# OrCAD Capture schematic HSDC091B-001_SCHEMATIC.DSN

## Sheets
1 1. PAGE1: size B; title: TMUXHS4212EVM; rev: A; note: HSDC091B
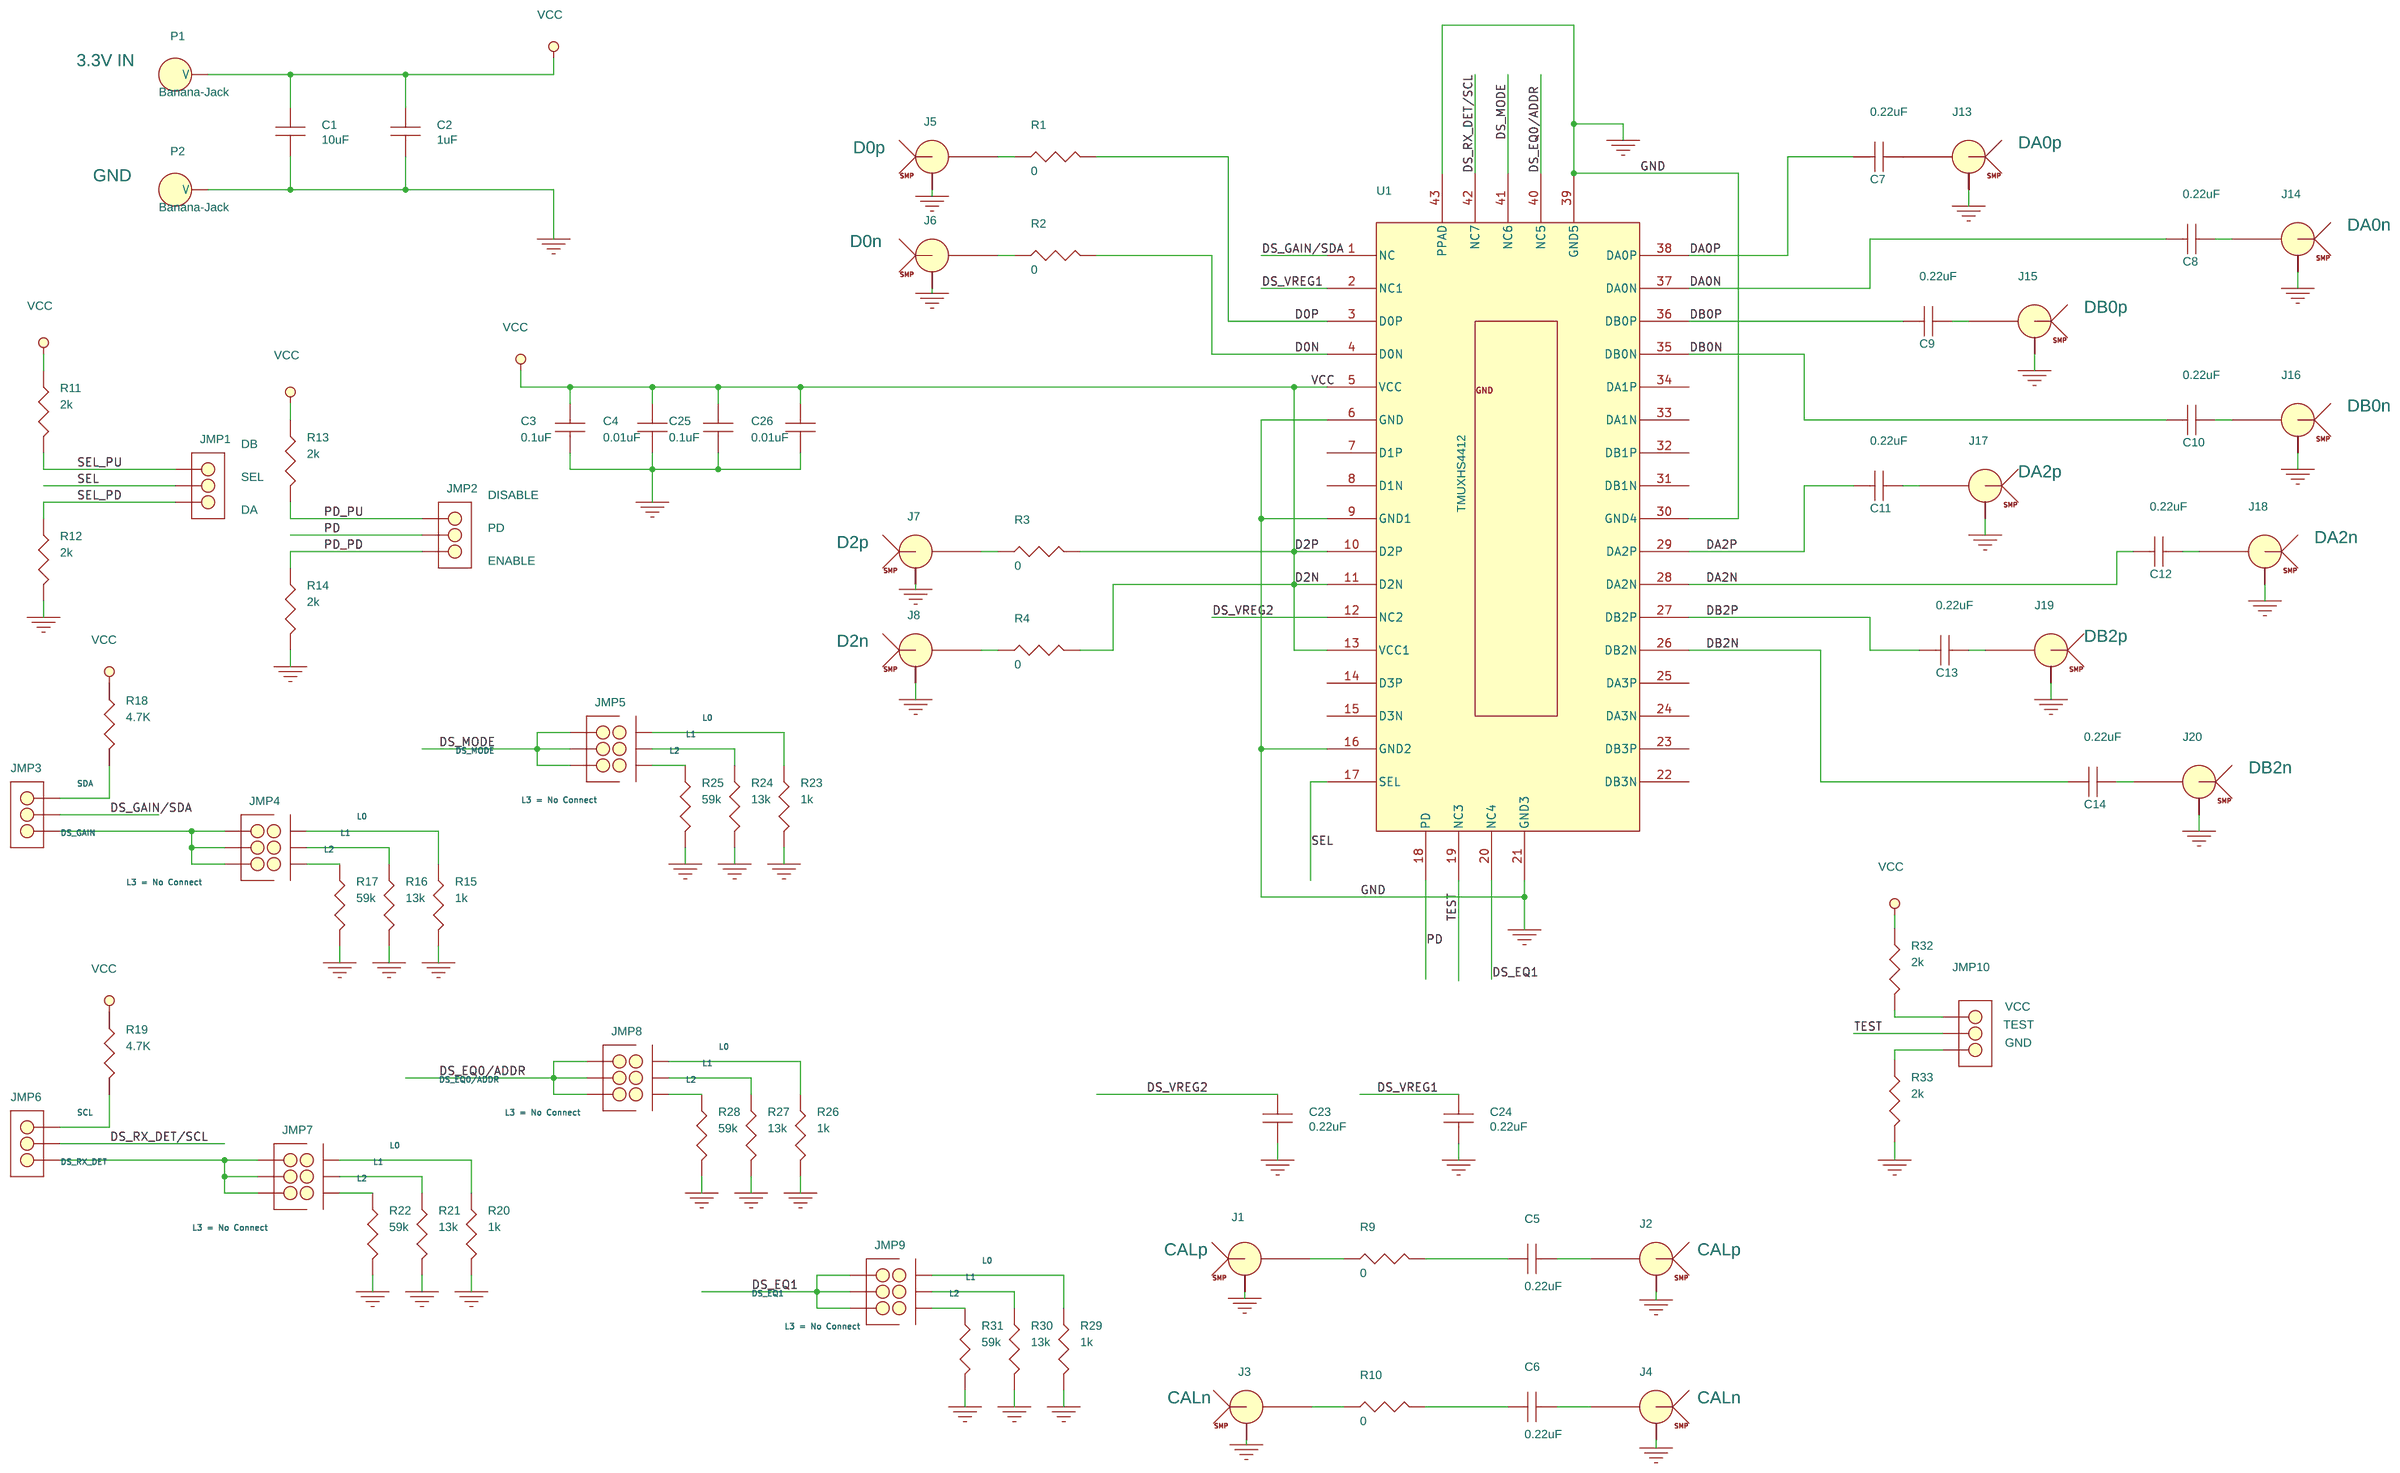
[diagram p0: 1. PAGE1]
2 2. HARDWARE: title: TMUXHS4412EVM - Hardware and Assembly Notes; note: HDSC091B
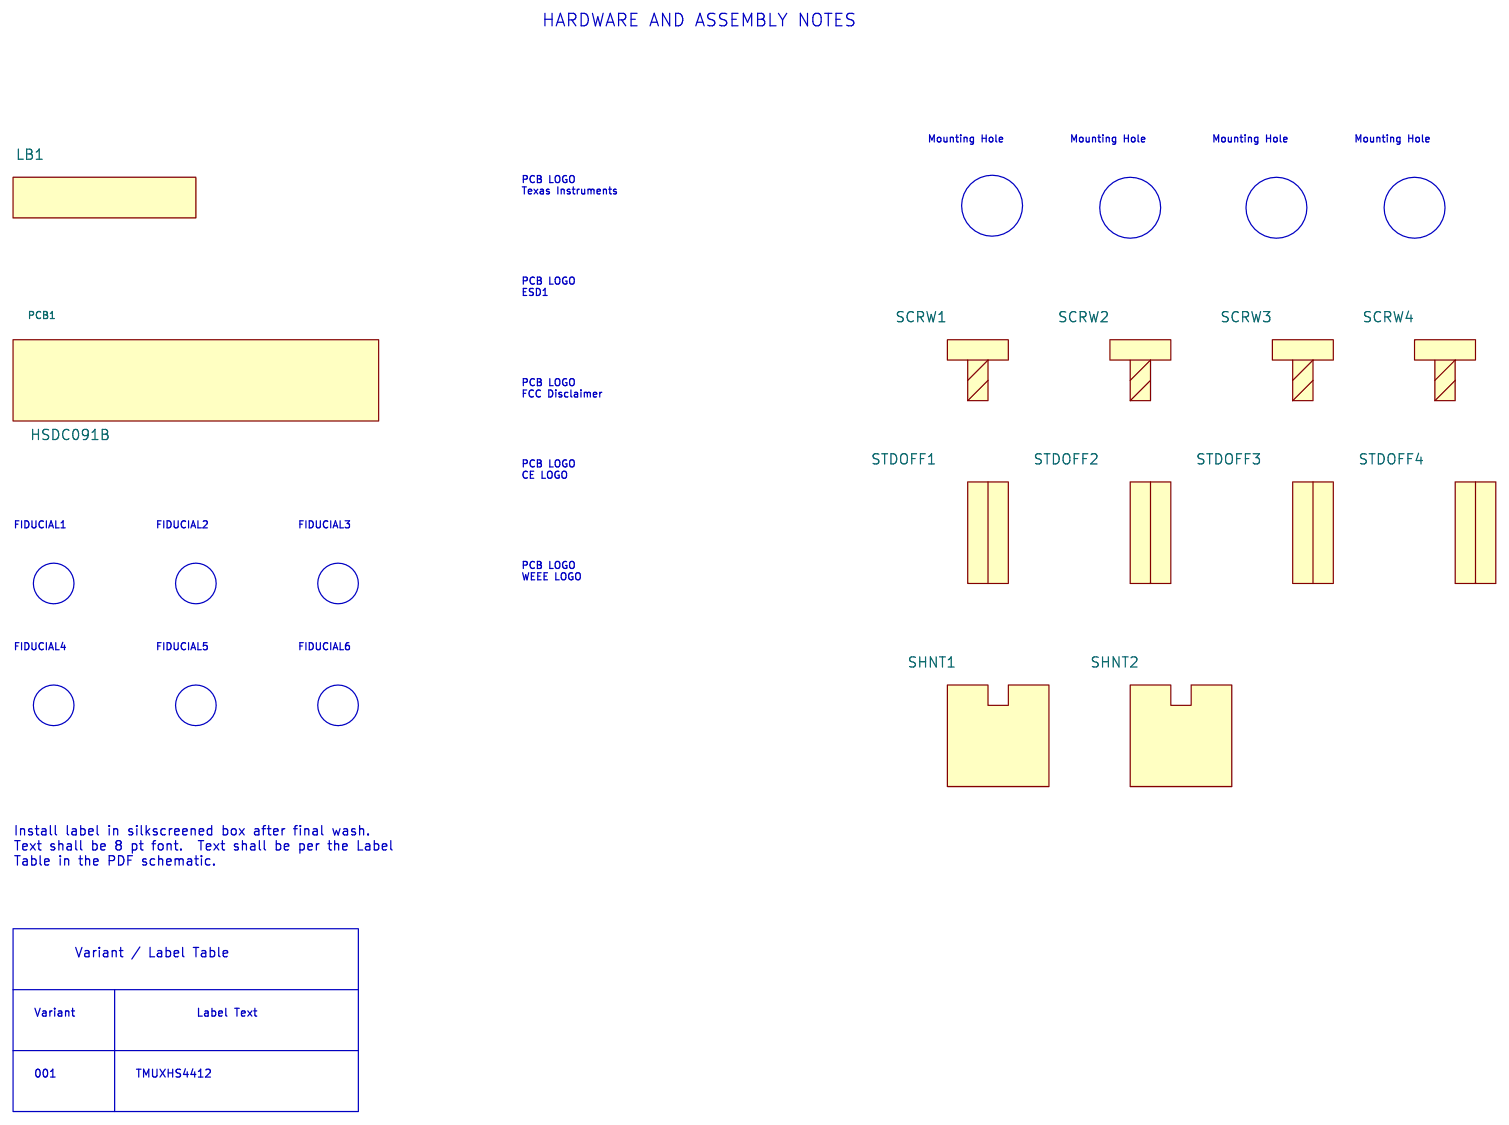
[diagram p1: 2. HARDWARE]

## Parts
sheet 1. PAGE1
C1  10uF  [cap_0603]
C2  1uF  [cap_0603]
C3  0.1uF  [cap_0402]
C4  0.01uF  [cap_0402]
C5  0.22uF  [cap_0201]
C6  0.22uF  [cap_0201]
C7  0.22uF  [cap_0201]
C8  0.22uF  [cap_0201]
C9  0.22uF  [cap_0201]
C10  0.22uF  [cap_0201]
C11  0.22uF  [cap_0201]
C12  0.22uF  [cap_0201]
C13  0.22uF  [cap_0201]
C14  0.22uF  [cap_0201]
C23  0.22uF  [cap_0603]
C24  0.22uF  [cap_0603]
C25  0.1uF  [cap_0402]
C26  0.01uF  [cap_0402]
J1  SMP  [CON_SMVT_19S101-40ML5_R04350]
J2  SMP  [CON_SMVT_19S101-40ML5_R04350]
J3  SMP  [CON_SMVT_19S101-40ML5_R04350]
J4  SMP  [CON_SMVT_19S101-40ML5_R04350]
J5  SMP  [CON_SMVT_19S101-40ML5_R04350]
J6  SMP  [CON_SMVT_19S101-40ML5_R04350]
J7  SMP  [CON_SMVT_19S101-40ML5_R04350]
J8  SMP  [CON_SMVT_19S101-40ML5_R04350]
J13  SMP  [CON_SMVT_19S101-40ML5_R04350]
J14  SMP  [CON_SMVT_19S101-40ML5_R04350]
J15  SMP  [CON_SMVT_19S101-40ML5_R04350]
J16  SMP  [CON_SMVT_19S101-40ML5_R04350]
J17  SMP  [CON_SMVT_19S101-40ML5_R04350]
J18  SMP  [CON_SMVT_19S101-40ML5_R04350]
J19  SMP  [CON_SMVT_19S101-40ML5_R04350]
J20  SMP  [CON_SMVT_19S101-40ML5_R04350]
JMP1  HDR3X1 M .1  [HDR_THVT_1X3_254_871]
JMP2  HDR3X1 M .1  [HDR_THVT_1X3_254_871]
JMP3  HDR3X1 M .1  [HDR_THVT_1X3_254_871]
JMP4  HDR3X1 M .1  [HDR_THVT_2X3_254_871]
JMP5  HDR3X1 M .1  [HDR_THVT_2X3_254_871]
JMP6  HDR3X1 M .1  [HDR_THVT_1X3_254_871]
JMP7  HDR3X1 M .1  [HDR_THVT_2X3_254_871]
JMP8  HDR3X1 M .1  [HDR_THVT_2X3_254_871]
JMP9  HDR3X1 M .1  [HDR_THVT_2X3_254_871]
JMP10  HDR3X1 M .1  [HDR_THVT_1X3_254_871]
P1  Banana-Jack  [BJ_THVT_3267]
P2  Banana-Jack  [BJ_THVT_3267]
R1  0  [res_0201]
R2  0  [res_0201]
R3  0  [res_0201]
R4  0  [res_0201]
R9  0  [res_0201]
R10  0  [res_0201]
R11  2k  [res_0402]
R12  2k  [res_0402]
R13  2k  [res_0402]
R14  2k  [res_0402]
R15  1k  [res_0402]
R16  13k  [res_0402]
R17  59k  [res_0402]
R18  4.7K  [res_0402]
R19  4.7K  [res_0402]
R20  1k  [res_0402]
R21  13k  [res_0402]
R22  59k  [res_0402]
R23  1k  [res_0402]
R24  13k  [res_0402]
R25  59k  [res_0402]
R26  1k  [res_0402]
R27  13k  [res_0402]
R28  59k  [res_0402]
R29  1k  [res_0402]
R30  13k  [res_0402]
R31  59k  [res_0402]
R32  2k  [res_0402]
R33  2k  [res_0402]
U1  TMUXHS4412  [RUA0042BA_205x755]
sheet 2. HARDWARE
LB1  PCB Label 0.650"H x 0.200"W  [rectangle]
PCB1  HSDC091B  [n/a]
SCRW1  NY PMS 440 005 PH  [screw]
SCRW2  NY PMS 440 005 PH  [screw]
SCRW3  NY PMS 440 005 PH  [screw]
SCRW4  NY PMS 440 005 PH  [screw]
SHNT1  QPC02SXGN-RC  [.1]
SHNT2  QPC02SXGN-RC  [.1]
STDOFF1  1902E  [Standoff]
STDOFF2  1902E  [Standoff]
STDOFF3  1902E  [Standoff]
STDOFF4  1902E  [Standoff]

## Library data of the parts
C1 = cc0603: Digikey: 587-1242-1-ND; Manufacturer: Murata; Manufacturer Part Number: GRM188R61A106KE69D
C2 C23 C24 = cc0603: Digikey: 587-1242-1-ND; Manufacturer: Taiyo Yuden; Manufacturer Part Number: LMK107B7105KA-T
C3 C25 = cc0402: Digikey: 311-1336-1-ND; Manufacturer: KEMET; Manufacturer Part Number: C0402C104M8RACTU
C4 C26 = cc0402: Digikey: 311-1336-1-ND; Manufacturer: KEMET; Manufacturer Part Number: C0402C103K8RACTU
C5-C14 = cc0201: Manufacturer: Taiyo Yuden; Manufacturer Part Number: LMK063BJ224MP-F
J1 J2 = SMP_0: Manufacturer Part Number: 19S101-40ML5; PART_NUMBER: 19S102-40ML5; SILKTEXT1: CALp
J3 J4 = SMP_0: Manufacturer Part Number: 19S101-40ML5; PART_NUMBER: 19S102-40ML5; SILKTEXT1: CALn
J5 = SMP_0: Manufacturer Part Number: 19S101-40ML5; PART_NUMBER: 19S102-40ML5; SILKTEXT1: D0p
J6 = SMP_0: Manufacturer Part Number: 19S101-40ML5; PART_NUMBER: 19S102-40ML5; SILKTEXT1: D0n
J7 = SMP_0: Manufacturer Part Number: 19S101-40ML5; PART_NUMBER: 19S102-40ML5; SILKTEXT1: D2p
J8 = SMP_0: Manufacturer Part Number: 19S101-40ML5; PART_NUMBER: 19S102-40ML5; SILKTEXT1: D2n
J13 = SMP_0: Manufacturer Part Number: 19S101-40ML5; PART_NUMBER: 19S102-40ML5; SILKTEXT1: DA0p
J14 = SMP_0: Manufacturer Part Number: 19S101-40ML5; PART_NUMBER: 19S102-40ML5; SILKTEXT1: DA0n
J15 = SMP_0: Manufacturer Part Number: 19S101-40ML5; PART_NUMBER: 19S102-40ML5; SILKTEXT1: DB0p
J16 = SMP_0: Manufacturer Part Number: 19S101-40ML5; PART_NUMBER: 19S102-40ML5; SILKTEXT1: DB0n
J17 = SMP_0: Manufacturer Part Number: 19S101-40ML5; PART_NUMBER: 19S102-40ML5; SILKTEXT1: DA2p
J18 = SMP_0: Manufacturer Part Number: 19S101-40ML5; PART_NUMBER: 19S102-40ML5; SILKTEXT1: DA2n
J19 = SMP_0: Manufacturer Part Number: 19S101-40ML5; PART_NUMBER: 19S102-40ML5; SILKTEXT1: DB2p
J20 = SMP_0: Manufacturer Part Number: 19S101-40ML5; PART_NUMBER: 19S102-40ML5; SILKTEXT1: DB2n
JMP1 = HDR3X1_M_.1: Digikey: S1012E-03-ND; Manufacturer: Samtec; Manufacturer Part Number: TSW-103-07-G-D; SILKTEXT1: DB; SILKTEXT2: SEL; SILKTEXT3: DA
JMP2 JMP3 JMP6 = HDR3X1_M_.1: Digikey: S1012E-03-ND; Manufacturer: Samtec; Manufacturer Part Number: TSW-103-07-G-D; SILKTEXT1: DISABLE; SILKTEXT2: PD; SILKTEXT3: ENABLE
JMP4 JMP5 JMP7 JMP9 = HDR3X1_M__2.1: Digikey: S1012E-03-ND; Manufacturer: Samtec; Manufacturer Part Number: TSW-103-07-G-D; SILKTEXT1: DISABLE; SILKTEXT2: PD; SILKTEXT3: ENABLE
JMP8 = HDR3X1_M__2.1: Digikey: S1012E-03-ND; Manufacturer: QPC02SXGN-RC; Manufacturer Part Number: PEC03SAAN; SILKTEXT1: DISABLE; SILKTEXT2: PD; SILKTEXT3: ENABLE
JMP10 = HDR3X1_M_.1: Digikey: S1012E-03-ND; Manufacturer: Samtec; Manufacturer Part Number: TSW-103-07-G-D; SILKTEXT1: VCC; SILKTEXT2: TEST; SILKTEXT3: GND
P1 = Banana-Jack: Manufacturer Part Number: 3267; SILKTEXT1: 3.3V IN
P2 = Banana-Jack: Manufacturer Part Number: 3267; SILKTEXT1: GND
R1-R4 R9 R10 = r0201: Manufacturer: Vishay Dale; Manufacturer Part Number: CRCW02010000Z0ED
R11-R33 = r0402: Digikey: 311-2.0KJRCT-ND; Manufacturer: Yageo; Manufacturer Part Number: RC0402JR-072KL
U1 = HD3SS3212_10: Manufacturer: Texas Instruments
LB1 = Label: Digikey: n/a; Manufacturer: Brady; Manufacturer Part Number: THT-14-423-10
PCB1 = PCB: Manufacturer: Any; Manufacturer Part Number: HSDC042
SCRW1-SCRW4 = Screw_40x.5_Nylon: Digikey: H546-ND; Manufacturer: B&F Fastener
SHNT1 SHNT2 = Shunt: Digikey: S9337-ND; Manufacturer: Sullins
STDOFF1-STDOFF4 = Standoff: Digikey: 36-1902E-ND; Manufacturer: Keystone

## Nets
GND: C1.2 C2.2 C3.2 C4.2 C23.2 C24.2 C25.2 C26.2 J1.2 J1.3 J1.4 J1.5 J1.6 J1.7 J1.8 J1.9 J1.10 J2.2 J2.3 J2.4 J2.5 J2.6 J2.7 J2.8 J2.9 J2.10 J3.2 J3.3 J3.4 J3.5 J3.6 J3.7 J3.8 J3.9 J3.10 J4.2 J4.3 J4.4 J4.5 J4.6 J4.7 J4.8 J4.9 J4.10 J5.2 J5.3 J5.4 J5.5 J5.6 J5.7 J5.8 J5.9 J5.10 J6.2 J6.3 J6.4 J6.5 J6.6 J6.7 J6.8 J6.9 J6.10 J7.2 J7.3 J7.4 J7.5 J7.6 J7.7 J7.8 J7.9 J7.10 J8.2 J8.3 J8.4 J8.5 J8.6 J8.7 J8.8 J8.9 J8.10 J13.2 J13.3 J13.4 J13.5 J13.6 J13.7 J13.8 J13.9 J13.10 J14.2 J14.3 J14.4 J14.5 J14.6 J14.7 J14.8 J14.9 J14.10 J15.2 J15.3 J15.4 J15.5 J15.6 J15.7 J15.8 J15.9 J15.10 J16.2 J16.3 J16.4 J16.5 J16.6 J16.7 J16.8 J16.9 J16.10 J17.2 J17.3 J17.4 J17.5 J17.6 J17.7 J17.8 J17.9 J17.10 J18.2 J18.3 J18.4 J18.5 J18.6 J18.7 J18.8 J18.9 J18.10 J19.2 J19.3 J19.4 J19.5 J19.6 J19.7 J19.8 J19.9 J19.10 J20.2 J20.3 J20.4 J20.5 J20.6 J20.7 J20.8 J20.9 J20.10 P2.1(V) R12.2 R14.2 R15.2 R16.2 R17.2 R20.2 R21.2 R22.2 R23.2 R24.2 R25.2 R26.2 R27.2 R28.2 R29.2 R30.2 R31.2 R33.2 U1.6(GND) U1.9(GND1) U1.16(GND2) U1.21(GND3) U1.30(GND4) U1.39(GND5) U1.43(PPAD)
VCC3P3: C1.1 C2.1 C3.1 C4.1 C25.1 C26.1 P1.1(V) R11.1 R13.1 R18.1 R19.1 R32.1 U1.5(VCC) U1.13(VCC1)
D0N: R2.2 U1.4(D0N)
D0P: R1.2 U1.3(D0P)
D2N: R4.2 U1.11(D2N)
D2P: R3.2 U1.10(D2P)
DA0N: C8.2 U1.37(DA0N)
DA0P: C7.2 U1.38(DA0P)
DA2N: C12.2 U1.28(DA2N)
DA2P: C11.2 U1.29(DA2P)
DB0N: C10.2 U1.35(DB0N)
DB0P: C9.2 U1.36(DB0P)
DB2N: C14.2 U1.26(DB2N)
DB2P: C13.2 U1.27(DB2P)
DS_EQ0/ADDR: JMP8.1 JMP8.3 JMP8.5 U1.40(NC5)
DS_EQ1: JMP9.1 JMP9.3 JMP9.5 U1.20(NC4)
DS_GAIN/SDA: JMP3.2 U1.1(NC)
DS_MODE: JMP5.1 JMP5.3 JMP5.5 U1.41(NC6)
DS_RX_DET/SCL: JMP6.2 U1.42(NC7)
DS_VREG1: C24.1 U1.2(NC1)
DS_VREG2: C23.1 U1.12(NC2)
PD: JMP2.2 U1.18(PD)
PD_PD: JMP2.3 R14.1
PD_PU: JMP2.1 R13.2
SEL: JMP1.2 U1.17(SEL)
SEL_PD: JMP1.3 R12.1
SEL_PU: JMP1.1 R11.2
TEST: JMP10.2 U1.19(NC3)
N04565: J6.1 R2.1
N04868: J7.1 R3.1
N04879: J8.1 R4.1
N102672: J5.1 R1.1
N16790356: J1.1 R9.1
N16790359: C5.1 R9.2
N16790362: C5.2 J2.1
N16790601: C6.1 R10.2
N16790603: C6.2 J4.1
N16798070: J3.1 R10.1
N16819141: C8.1 J14.1
N16819616: C10.1 J16.1
N16819620: C9.1 J15.1
N16819971: C11.1 J17.1
N16819975: C12.1 J18.1
N16820243: C13.1 J19.1
N16820247: C14.1 J20.1
N16832703: JMP3.1 R18.2
N16832833: JMP6.1 R19.2
N16847290: JMP5.6 R25.1
N16847293: JMP5.4 R24.1
N16847298: JMP5.2 R23.1
N16847609: JMP8.2 R26.1
N16847613: JMP8.4 R27.1
N16847617: JMP8.6 R28.1
N16848254: JMP9.2 R29.1
N16848258: JMP9.4 R30.1
N16848262: JMP9.6 R31.1
N16848700: JMP3.3 JMP4.1 JMP4.3 JMP4.5
N16848778: JMP4.2 R15.1
N16848782: JMP4.4 R16.1
N16848786: JMP4.6 R17.1
N16849265: JMP6.3 JMP7.1 JMP7.3 JMP7.5
N16849344: JMP7.2 R20.1
N16849348: JMP7.4 R21.1
N16849352: JMP7.6 R22.1
N16856700: C7.1 J13.1
N16857633: JMP10.1 R32.2
N16857638: JMP10.3 R33.1

Not connected (* = marked no-connect by the designer): U1 7(D1P) 8(D1N) 14(D3P) 15(D3N) 22(DB3N) 23(DB3P) 24(DA3N) 25(DA3P) 31(DB1N) 32(DB1P) 33(DA1N) 34(DA1P)

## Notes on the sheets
sheet 1
- L0
- L1
- DS_MODE
- L2
- SDA
- L3 = No Connect
- DS_GAIN
- L1
- L0
- L2
- L3 = No Connect
- L0
- L1
- DS_EQ0/ADDR
- L2
- SCL
- L3 = No Connect
- DS_RX_DET
- L1
- L0
- L2
- L3 = No Connect
- L0
- L1
- DS_EQ1
- L2
- L3 = No Connect
sheet 2
- HARDWARE AND ASSEMBLY NOTES
- Mounting Hole
- Mounting Hole
- Mounting Hole
- Mounting Hole
- PCB LOGO
  Texas Instruments
- PCB LOGO
  ESD1
- PCB LOGO
  FCC Disclaimer
- PCB LOGO
  CE LOGO
- FIDUCIAL1
- FIDUCIAL2
- FIDUCIAL3
- PCB LOGO
  WEEE LOGO
- FIDUCIAL4
- FIDUCIAL5
- FIDUCIAL6
- Install label in silkscreened box after final wash.
  Text shall be 8 pt font.  Text shall be per the Label
  Table in the PDF schematic.
- Variant / Label Table
- Variant
- Label Text
- 001
- TMUXHS4412
